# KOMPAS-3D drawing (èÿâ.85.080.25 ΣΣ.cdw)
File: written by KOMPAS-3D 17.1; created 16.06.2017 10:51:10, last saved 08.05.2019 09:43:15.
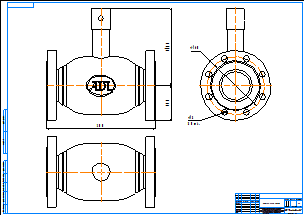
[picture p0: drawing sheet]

Sheet 1: A1, landscape

Title block, sheet 1: name: КШГ.85.080.25 фф; material: Внимание! Данный продукт является объектом авторского права ООО «Торговый Дом АДЛ». / Запрещается изменение, копирование, распространение / (в том числе путем копирования на другие сайты и ресурсы в Интернете) / или любое иное использование информации и объектов без предварительного / согласия правообладателя (ООО «Торговый Дом АДЛ»).; scale: 1:1; sheets: 1; organisation: ООО "Торговый дом АДЛ"; sheet format: A1; stored path: C:\Users\tra\Desktop\2д чертежи\Шаровые краны БИВАЛ\КШ_Бивал_серия_82_85\KOMPAS 2D\КШГ.85.080.25 фф.cdw

Views: Спереди 1, Проекционный вид 2, Проекционный вид 3
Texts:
  Klimkovich
  ADL
Dimensions and other numbers on the sheet: 300; 214,6; 97,5; 160; 18; 8 Отв.; 1:1; 1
